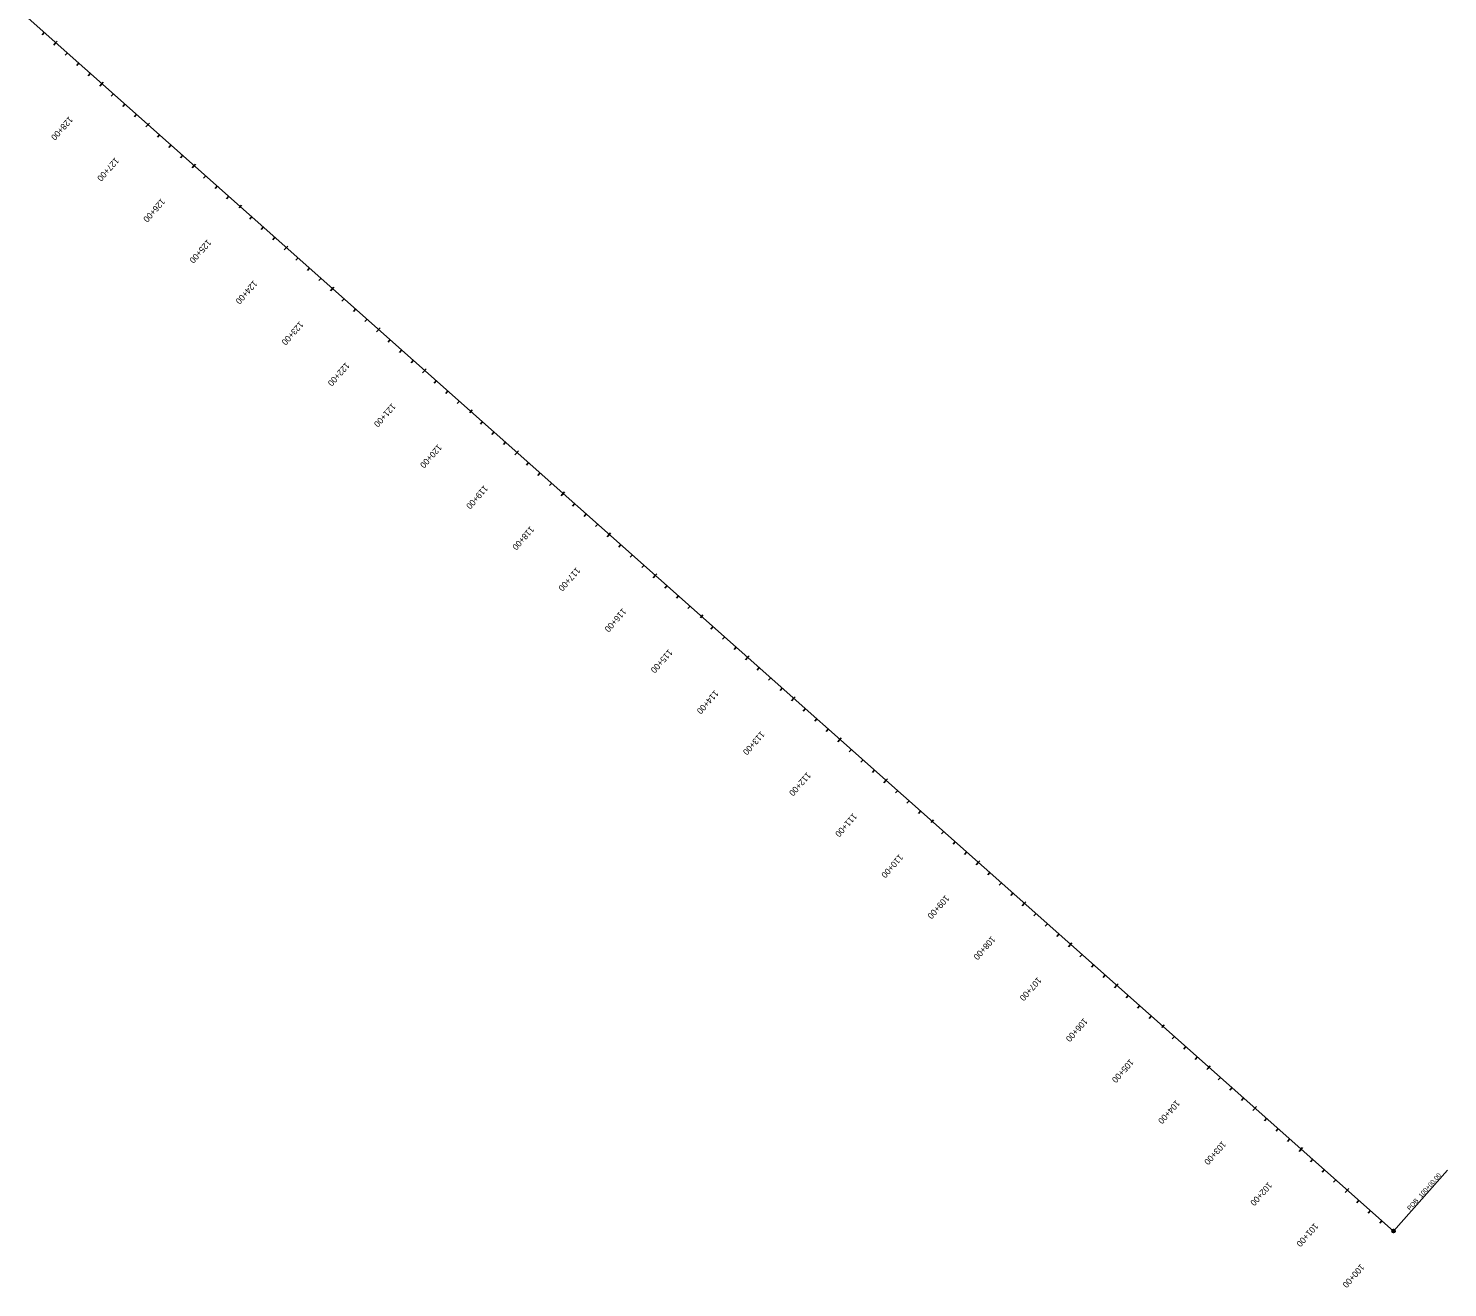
# Model space of a CAD drawing. Extents: x 5226274 to 5237131, y 3641705 to 3648830.
# Drawn here: x 5234830 to 5237131, y 3641705 to 3643746 of the extents above; entities that cross this region are included whole.
import ezdxf

# ---------------------------------------------------------------- set-up
doc = ezdxf.new("R2010")
doc.units = 0
for name, color, linetype in [('Alignment', 7, 'Continuous'), ('TextAlignment', 7, 'Continuous'), ('TextAlignmentLrg', 7, 'Continuous'), ('TextAlignmentSml', 7, 'Continuous')]:
    doc.layers.add(name, color=color, linetype=linetype)

msp = doc.modelspace()

# ---------------------------------------------------------------- linework, layer by layer
at = {"layer": 'Alignment'}
for q in [(5232496.9, 3645834.9), (5233201.4, 3645209.2)]:
    msp.add_line((5237043, 3641797.1), q, dxfattribs=at)
at = {"layer": 'TextAlignment'}
for p in [(5237043, 3641797.1), (5237130.7, 3641895.8)]:
    msp.add_line(p, (5237130.7, 3641895.8), dxfattribs=at)
msp.add_circle((5237043, 3641797.1), 2.67, dxfattribs=at)
at = {"layer": 'TextAlignmentLrg'}
for p, q in [((5234874.8, 3643722.9), (5234871.2, 3643718.8)), ((5234949.6, 3643656.5), (5234945.9, 3643652.4)), ((5235024.3, 3643590.1), (5235020.7, 3643586)), ((5235099.1, 3643523.7), (5235095.5, 3643519.6)), ((5235171.8, 3643455), (5235175.9, 3643459.5)), ((5235248.6, 3643390.9), (5235245, 3643386.8)), ((5235323.4, 3643324.4), (5235319.8, 3643320.4)), ((5235398.2, 3643258), (5235394.5, 3643254)), ((5235472.9, 3643191.6), (5235469.3, 3643187.5)), ((5235545.7, 3643122.9), (5235549.7, 3643127.5)), ((5235622.5, 3643058.8), (5235618.8, 3643054.7)), ((5235697.2, 3642992.4), (5235693.6, 3642988.3)), ((5235772, 3642926), (5235768.4, 3642921.9)), ((5235846.8, 3642859.6), (5235843.1, 3642855.5)), ((5235919.5, 3642790.9), (5235923.6, 3642795.5)), ((5235996.3, 3642726.8), (5235992.7, 3642722.7)), ((5236071.1, 3642660.4), (5236067.4, 3642656.3)), ((5236145.8, 3642594), (5236142.2, 3642589.9)), ((5236220.6, 3642527.5), (5236217, 3642523.5)), ((5236293.3, 3642458.9), (5236297.4, 3642463.4)), ((5236370.1, 3642394.7), (5236366.5, 3642390.7)), ((5236444.9, 3642328.3), (5236441.3, 3642324.2)), ((5236519.7, 3642261.9), (5236516, 3642257.8)), ((5236594.4, 3642195.5), (5236590.8, 3642191.4)), ((5236667.2, 3642126.8), (5236671.2, 3642131.4)), ((5236744, 3642062.7), (5236740.3, 3642058.6)), ((5236818.7, 3641996.3), (5236815.1, 3641992.2)), ((5236893.5, 3641929.9), (5236889.9, 3641925.8)), ((5236968.2, 3641863.5), (5236964.6, 3641859.4)), ((5237041, 3641794.8), (5237045, 3641799.4))]:
    msp.add_line(p, q, dxfattribs=at)
at = {"layer": 'TextAlignmentSml'}
for p, q in [((5234856.1, 3643739.5), (5234852.5, 3643735.4)), ((5234872.8, 3643720.6), (5234876.8, 3643725.2)), ((5234893.5, 3643706.3), (5234889.9, 3643702.2)), ((5234912.2, 3643689.7), (5234908.5, 3643685.6)), ((5234930.9, 3643673.1), (5234927.2, 3643669)), ((5234947.5, 3643654.2), (5234951.6, 3643658.8)), ((5234968.2, 3643639.9), (5234964.6, 3643635.8)), ((5234986.9, 3643623.3), (5234983.3, 3643619.2)), ((5235005.6, 3643606.7), (5235002, 3643602.6)), ((5235022.3, 3643587.8), (5235026.4, 3643592.4)), ((5235043, 3643573.5), (5235039.4, 3643569.4)), ((5235061.7, 3643556.9), (5235058.1, 3643552.8)), ((5235080.4, 3643540.3), (5235076.8, 3643536.2)), ((5235097.1, 3643521.4), (5235101.1, 3643526)), ((5235117.8, 3643507.1), (5235114.2, 3643503)), ((5235136.5, 3643490.5), (5235132.8, 3643486.4)), ((5235155.2, 3643473.9), (5235151.5, 3643469.8)), ((5235171.8, 3643455), (5235175.9, 3643459.5)), ((5235192.5, 3643440.7), (5235188.9, 3643436.6)), ((5235211.2, 3643424.1), (5235207.6, 3643420)), ((5235229.9, 3643407.5), (5235226.3, 3643403.4)), ((5235246.6, 3643388.6), (5235250.7, 3643393.1)), ((5235267.3, 3643374.2), (5235263.7, 3643370.2)), ((5235286, 3643357.6), (5235282.4, 3643353.6)), ((5235304.7, 3643341), (5235301.1, 3643337)), ((5235321.4, 3643322.2), (5235325.4, 3643326.7)), ((5235342.1, 3643307.8), (5235338.5, 3643303.8)), ((5235360.8, 3643291.2), (5235357.1, 3643287.2)), ((5235379.5, 3643274.6), (5235375.8, 3643270.6)), ((5235396.1, 3643255.7), (5235400.2, 3643260.3)), ((5235416.8, 3643241.4), (5235413.2, 3643237.4)), ((5235435.5, 3643224.8), (5235431.9, 3643220.7)), ((5235454.2, 3643208.2), (5235450.6, 3643204.1)), ((5235470.9, 3643189.3), (5235475, 3643193.9)), ((5235491.6, 3643175), (5235488, 3643170.9)), ((5235510.3, 3643158.4), (5235506.7, 3643154.3)), ((5235529, 3643141.8), (5235525.4, 3643137.7)), ((5235545.7, 3643122.9), (5235549.7, 3643127.5)), ((5235566.4, 3643108.6), (5235562.8, 3643104.5)), ((5235585.1, 3643092), (5235581.4, 3643087.9)), ((5235603.8, 3643075.4), (5235600.1, 3643071.3)), ((5235620.4, 3643056.5), (5235624.5, 3643061.1)), ((5235641.1, 3643042.2), (5235637.5, 3643038.1)), ((5235659.8, 3643025.6), (5235656.2, 3643021.5)), ((5235678.5, 3643009), (5235674.9, 3643004.9)), ((5235695.2, 3642990.1), (5235699.3, 3642994.7)), ((5235715.9, 3642975.8), (5235712.3, 3642971.7)), ((5235734.6, 3642959.2), (5235731, 3642955.1)), ((5235753.3, 3642942.6), (5235749.7, 3642938.5)), ((5235770, 3642923.7), (5235774, 3642928.3)), ((5235790.7, 3642909.4), (5235787.1, 3642905.3)), ((5235809.4, 3642892.8), (5235805.7, 3642888.7)), ((5235828.1, 3642876.2), (5235824.4, 3642872.1)), ((5235844.7, 3642857.3), (5235848.8, 3642861.9)), ((5235865.4, 3642843), (5235861.8, 3642838.9)), ((5235884.1, 3642826.4), (5235880.5, 3642822.3)), ((5235902.8, 3642809.8), (5235899.2, 3642805.7)), ((5235919.5, 3642790.9), (5235923.6, 3642795.5)), ((5235940.2, 3642776.6), (5235936.6, 3642772.5)), ((5235958.9, 3642760), (5235955.3, 3642755.9)), ((5235977.6, 3642743.4), (5235974, 3642739.3)), ((5235994.3, 3642724.5), (5235998.3, 3642729.1)), ((5236015, 3642710.2), (5236011.4, 3642706.1)), ((5236033.7, 3642693.6), (5236030, 3642689.5)), ((5236052.4, 3642677), (5236048.7, 3642672.9)), ((5236069, 3642658.1), (5236073.1, 3642662.7)), ((5236089.7, 3642643.8), (5236086.1, 3642639.7)), ((5236108.4, 3642627.2), (5236104.8, 3642623.1)), ((5236127.1, 3642610.6), (5236123.5, 3642606.5)), ((5236143.8, 3642591.7), (5236147.9, 3642596.2)), ((5236164.5, 3642577.4), (5236160.9, 3642573.3)), ((5236183.2, 3642560.8), (5236179.6, 3642556.7)), ((5236201.9, 3642544.2), (5236198.3, 3642540.1)), ((5236218.6, 3642525.3), (5236222.6, 3642529.8)), ((5236239.3, 3642510.9), (5236235.7, 3642506.9)), ((5236258, 3642494.3), (5236254.3, 3642490.3)), ((5236276.7, 3642477.7), (5236273, 3642473.7)), ((5236293.3, 3642458.9), (5236297.4, 3642463.4)), ((5236314, 3642444.5), (5236310.4, 3642440.5)), ((5236332.7, 3642427.9), (5236329.1, 3642423.9)), ((5236351.4, 3642411.3), (5236347.8, 3642407.3)), ((5236368.1, 3642392.4), (5236372.2, 3642397)), ((5236388.8, 3642378.1), (5236385.2, 3642374.1)), ((5236407.5, 3642361.5), (5236403.9, 3642357.4)), ((5236426.2, 3642344.9), (5236422.6, 3642340.8)), ((5236442.9, 3642326), (5236446.9, 3642330.6)), ((5236463.6, 3642311.7), (5236460, 3642307.6)), ((5236482.3, 3642295.1), (5236478.6, 3642291)), ((5236501, 3642278.5), (5236497.3, 3642274.4)), ((5236517.6, 3642259.6), (5236521.7, 3642264.2)), ((5236538.3, 3642245.3), (5236534.7, 3642241.2)), ((5236557, 3642228.7), (5236553.4, 3642224.6)), ((5236575.7, 3642212.1), (5236572.1, 3642208)), ((5236592.4, 3642193.2), (5236596.4, 3642197.8)), ((5236613.1, 3642178.9), (5236609.5, 3642174.8)), ((5236631.8, 3642162.3), (5236628.2, 3642158.2)), ((5236650.5, 3642145.7), (5236646.9, 3642141.6)), ((5236667.2, 3642126.8), (5236671.2, 3642131.4)), ((5236687.9, 3642112.5), (5236684.2, 3642108.4)), ((5236706.6, 3642095.9), (5236702.9, 3642091.8)), ((5236725.3, 3642079.3), (5236721.6, 3642075.2)), ((5236741.9, 3642060.4), (5236746, 3642065)), ((5236762.6, 3642046.1), (5236759, 3642042)), ((5236781.3, 3642029.5), (5236777.7, 3642025.4)), ((5236800, 3642012.9), (5236796.4, 3642008.8)), ((5236816.7, 3641994), (5236820.7, 3641998.6)), ((5236837.4, 3641979.7), (5236833.8, 3641975.6)), ((5236856.1, 3641963.1), (5236852.5, 3641959)), ((5236874.8, 3641946.5), (5236871.2, 3641942.4)), ((5236891.5, 3641927.6), (5236895.5, 3641932.2)), ((5236912.2, 3641913.3), (5236908.5, 3641909.2)), ((5236930.9, 3641896.7), (5236927.2, 3641892.6)), ((5236949.6, 3641880.1), (5236945.9, 3641876)), ((5236966.2, 3641861.2), (5236970.3, 3641865.8)), ((5236986.9, 3641846.9), (5236983.3, 3641842.8)), ((5237005.6, 3641830.3), (5237002, 3641826.2)), ((5237024.3, 3641813.7), (5237020.7, 3641809.6)), ((5237041, 3641794.8), (5237045, 3641799.4))]:
    msp.add_line(p, q, dxfattribs=at)

# ---------------------------------------------------------------- texts
at = {"layer": 'TextAlignment'}
for s, p in [('100+00.00', (5237088.1, 3641850.3)), ('POB ', (5237069.7, 3641829.6))]:
    msp.add_text(s, height=7.5, rotation=48.3884, dxfattribs=at).set_placement(p)
at = {"layer": 'TextAlignmentLrg'}
for s, p in [('125+00', (5235120.3, 3643404.5)), ('120+00', (5235494.1, 3643072.5)), ('115+00', (5235868, 3642740.4)), ('110+00', (5236241.8, 3642408.4)), ('105+00', (5236615.6, 3642076.4)), ('100+00', (5236989.5, 3641744.3))]:
    msp.add_text(s, height=10.02, rotation=228.3884, dxfattribs=at).set_placement(p)
at = {"layer": 'TextAlignmentSml'}
for s, p in [('128+00', (5234896, 3643603.7)), ('127+00', (5234970.8, 3643537.3)), ('126+00', (5235045.5, 3643470.9)), ('125+00', (5235120.3, 3643404.5)), ('124+00', (5235195.1, 3643338.1)), ('123+00', (5235269.8, 3643271.7)), ('122+00', (5235344.6, 3643205.3)), ('121+00', (5235419.4, 3643138.9)), ('120+00', (5235494.1, 3643072.5)), ('119+00', (5235568.9, 3643006.1)), ('118+00', (5235643.7, 3642939.7)), ('117+00', (5235718.4, 3642873.2)), ('116+00', (5235793.2, 3642806.8)), ('115+00', (5235868, 3642740.4)), ('114+00', (5235942.7, 3642674)), ('113+00', (5236017.5, 3642607.6)), ('112+00', (5236092.3, 3642541.2)), ('111+00', (5236167, 3642474.8)), ('110+00', (5236241.8, 3642408.4)), ('109+00', (5236316.6, 3642342)), ('108+00', (5236391.3, 3642275.6)), ('107+00', (5236466.1, 3642209.2)), ('106+00', (5236540.9, 3642142.8)), ('105+00', (5236615.6, 3642076.4)), ('104+00', (5236690.4, 3642009.9)), ('103+00', (5236765.2, 3641943.5)), ('102+00', (5236839.9, 3641877.1)), ('101+00', (5236914.7, 3641810.7)), ('100+00', (5236989.5, 3641744.3))]:
    msp.add_text(s, height=10.02, rotation=228.3884, dxfattribs=at).set_placement(p)

doc.saveas('drawing.dxf')
